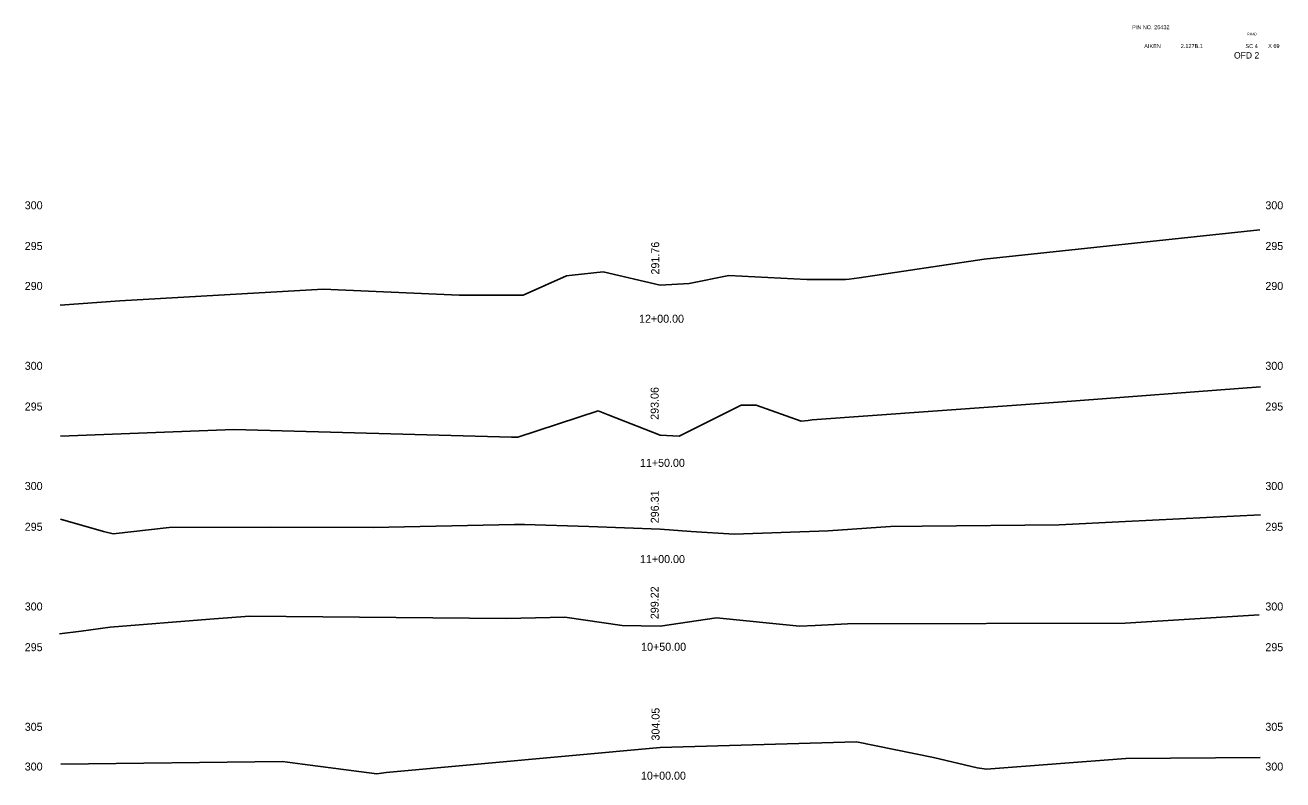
# Model space of a CAD drawing. Extents: x 1001 to 1158, y 1010 to 1104.
import ezdxf

# ---------------------------------------------------------------- set-up
doc = ezdxf.new("R2010")
doc.units = 0
for name, color, linetype in [('Level 1', 7, 'Continuous'), ('Level 10', 7, 'Continuous'), ('Level 3', 7, 'Continuous'), ('Level 60', 7, 'Continuous')]:
    doc.layers.add(name, color=color, linetype=linetype)

msp = doc.modelspace()

# ---------------------------------------------------------------- linework, layer by layer
at = {"layer": 'Level 60'}
for p, q in [((1120.46, 1075.02), (1154.88, 1078.69)), ((1104.85, 1072.68), (1120.46, 1075.02)), ((1062.88, 1070.54), (1068.28, 1072.94)), ((1068.28, 1072.94), (1069.01, 1073.03)), ((1069.01, 1073.03), (1072.87, 1073.45)), ((1072.87, 1073.45), (1080, 1071.76)), ((1083.63, 1071.98), (1088.56, 1072.97)), ((1088.56, 1072.97), (1098.31, 1072.48)), ((1080, 1071.76), (1083.63, 1071.98)), ((1098.31, 1072.48), (1103.14, 1072.48)), ((1103.14, 1072.48), (1103.58, 1072.52)), ((1103.58, 1072.52), (1104.85, 1072.68)), ((1005.04, 1069.26), (1012.49, 1069.83)), ((1012.49, 1069.83), (1037.88, 1071.26)), ((1037.88, 1071.26), (1054.9, 1070.52)), ((1054.9, 1070.52), (1062.88, 1070.54)), ((1129.69, 1057.18), (1154.97, 1059.09)), ((1062.19, 1052.81), (1072.23, 1056.07)), ((1072.23, 1056.07), (1073.48, 1055.59)), ((1082.37, 1052.91), (1090.1, 1056.78)), ((1090.1, 1056.78), (1091.99, 1056.77)), ((1091.99, 1056.77), (1097.61, 1054.81)), ((1098.97, 1054.96), (1129.69, 1057.18)), ((1073.48, 1055.59), (1080, 1053.06)), ((1097.61, 1054.81), (1098.47, 1054.89)), ((1098.47, 1054.89), (1098.97, 1054.96)), ((1005.07, 1052.91), (1026.74, 1053.77)), ((1026.74, 1053.77), (1061.4, 1052.81)), ((1061.4, 1052.81), (1062.19, 1052.81)), ((1080, 1053.06), (1082.37, 1052.91)), ((1138.13, 1042.25), (1154.97, 1043.1)), ((1005.09, 1042.57), (1010.45, 1041.04)), ((1018.66, 1041.52), (1031.35, 1041.56)), ((1031.35, 1041.56), (1044.15, 1041.52)), ((1044.15, 1041.52), (1061.8, 1041.9)), ((1061.8, 1041.9), (1062.39, 1041.9)), ((1062.39, 1041.9), (1063.03, 1041.88)), ((1063.03, 1041.88), (1071.09, 1041.63)), ((1071.09, 1041.63), (1080, 1041.31)), ((1100.99, 1041.12), (1108.75, 1041.63)), ((1108.75, 1041.63), (1112.7, 1041.69)), ((1112.7, 1041.69), (1129.83, 1041.85)), ((1129.83, 1041.85), (1138.13, 1042.25)), ((1010.45, 1041.04), (1011.68, 1040.72)), ((1011.68, 1040.72), (1018.66, 1041.52)), ((1080, 1041.31), (1083.87, 1041.04)), ((1083.87, 1041.04), (1089.23, 1040.68)), ((1089.23, 1040.68), (1100.99, 1041.12)), ((1138.06, 1029.59), (1154.82, 1030.63)), ((1007.67, 1028.57), (1011.31, 1029.08)), ((1011.31, 1029.08), (1023.73, 1030.06)), ((1023.73, 1030.06), (1028.68, 1030.47)), ((1028.68, 1030.47), (1060.77, 1030.15)), ((1060.77, 1030.15), (1068.07, 1030.32)), ((1068.07, 1030.32), (1075.25, 1029.3)), ((1075.25, 1029.3), (1080, 1029.22)), ((1080, 1029.22), (1087.04, 1030.23)), ((1087.04, 1030.23), (1097.39, 1029.22)), ((1097.39, 1029.22), (1099.34, 1029.3)), ((1099.34, 1029.3), (1103.39, 1029.49)), ((1103.39, 1029.49), (1138.06, 1029.59)), ((1004.98, 1028.23), (1007.67, 1028.57)), ((1045.76, 1010.93), (1080, 1014.05)), ((1080, 1014.05), (1104.51, 1014.75)), ((1104.51, 1014.75), (1114.11, 1012.79)), ((1005.12, 1011.96), (1032.83, 1012.33)), ((1032.83, 1012.33), (1035.32, 1011.97)), ((1035.32, 1011.97), (1044.6, 1010.75)), ((1114.11, 1012.79), (1119.58, 1011.5)), ((1120.75, 1011.34), (1138.17, 1012.69)), ((1138.17, 1012.69), (1154.92, 1012.79)), ((1044.6, 1010.75), (1045.76, 1010.93)), ((1119.58, 1011.5), (1120.75, 1011.34))]:
    msp.add_line(p, q, dxfattribs=at)

# ---------------------------------------------------------------- texts
at = {"layer": 'Level 1'}
for s, height, p in [('PIN NO. 26432', 0.5, (1138.93, 1103.72)), ('ROAD', 0.3, (1153.33, 1102.97)), ('AIKEN', 0.5, (1140.45, 1101.36)), (' 2.127B.1', 0.5, (1144.82, 1101.36)), ('SC 4', 0.5, (1153.1, 1101.36)), ('X 69', 0.5, (1155.93, 1101.38)), ('OFD 2', 0.8, (1151.66, 1100.06))]:
    msp.add_text(s, height=height, dxfattribs=at).set_placement(p)
at = {"layer": 'Level 10'}
for s, p in [('291.76', (1079.87, 1073.1)), ('293.06', (1079.8, 1054.96)), ('296.31', (1079.82, 1042.05)), ('299.22', (1079.8, 1030.08)), ('304.05', (1079.91, 1014.93))]:
    msp.add_text(s, height=1, rotation=90, dxfattribs=at).set_placement(p)
for s, p in [('12+00.00', (1077.35, 1067.08)), ('11+50.00', (1077.46, 1049.09)), ('11+00.00', (1077.47, 1037.08)), ('10+50.00', (1077.61, 1026.13)), ('10+00.00', (1077.59, 1010.04))]:
    msp.add_text(s, height=1, dxfattribs=at).set_placement(p)
at = {"layer": 'Level 3'}
for s, p in [(' 300', (1000.25, 1081.24)), (' 300', (1155.21, 1081.24)), (' 295', (1000.25, 1076.16)), (' 295', (1155.21, 1076.16)), (' 290', (1000.25, 1071.17)), (' 290', (1155.21, 1071.17)), (' 300', (1000.25, 1061.2)), (' 300', (1155.21, 1061.2)), (' 295', (1000.25, 1056.12)), (' 295', (1155.21, 1056.12)), (' 300', (1000.25, 1046.2)), (' 300', (1155.21, 1046.2)), (' 295', (1000.25, 1041.11)), (' 295', (1155.21, 1041.11)), (' 300', (1000.25, 1031.16)), (' 300', (1155.21, 1031.16)), (' 295', (1000.25, 1026.08)), (' 295', (1155.21, 1026.08)), (' 305', (1000.25, 1016.14)), (' 305', (1155.21, 1016.14)), (' 300', (1000.25, 1011.18)), (' 300', (1155.21, 1011.18))]:
    msp.add_text(s, height=1, dxfattribs=at).set_placement(p)

doc.saveas('drawing.dxf')
